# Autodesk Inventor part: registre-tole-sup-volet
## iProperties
Author: chr
Created: 2001-06
Part Number: registre-tole-sup-volet
Material: Par défaut
Document SubType Name: Tôlerie
Designer: chr
Control State: 0
Master: False
Checked Out: False
PropertySet Name: Design Tracking Control
Shininess: 21.0
PropertySet Name: _Private Model Information
Length Units: 11269
Angle Units: 11286
Time Units: 11279
Mass Units: 11290
Length Display Precision: 3
Angle Display Precision: 2
Compacted: False
Density: 0.0
Volumn: 0.0
Area: 0.0
PropertySet Name: Model Information
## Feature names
1. Ouverture1
2. Symétrie1 [Mirror]
3. Perçage1 [Hole]
4. Réseau rectangulaire1 [Rectangular Pattern]
5. Plaque1
